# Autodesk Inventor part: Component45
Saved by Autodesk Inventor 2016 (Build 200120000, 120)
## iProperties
Created: 2016-09
Part Number: Component45
Material: Generic
Document SubType Name: Modeling
Designer: Administrator
Appearance: Generic
Author: Administrator
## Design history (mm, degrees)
feature "Body1"
body "Solid1"
